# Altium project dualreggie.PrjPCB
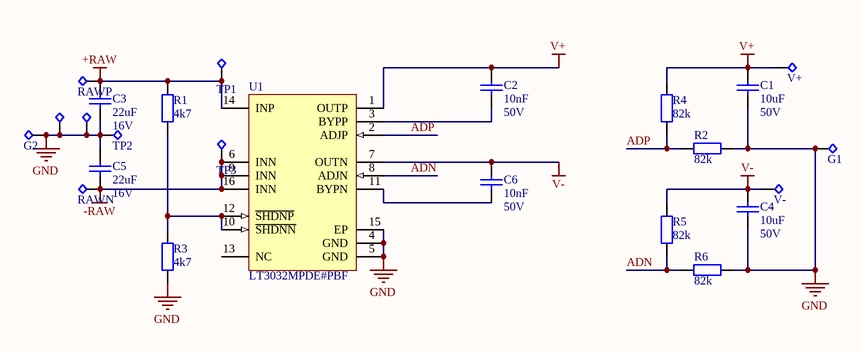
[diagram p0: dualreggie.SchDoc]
1 sheet, 24 parts. Net scope: global (net labels, ports and power ports of the same name join across sheets).
Board file: dualreggie.PcbDoc

## Sheet dualreggie.SchDoc
size A0

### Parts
C1  10uF  Voltage rating: 50V  [CC1210N1X]
C2  10nF  Voltage rating: 50V  [CC0402N1X]
C3  22uF  Voltage rating: 16V  [CC0805N1R]
C4  10uF  Voltage rating: 50V  [CC1210N1X]
C5  22uF  Voltage rating: 16V  [CC0805N1R]
C6  10nF  Voltage rating: 50V  [CC0402N1X]
G1  TP 0.5mm  [SP2.0]  (value not drawn)  (no BOM)
G2  TP 0.5mm  [SP2.0]  (value not drawn)  (no BOM)
GND1  TP 0.5mm  [TPH0.5S]  (value not drawn)  (no BOM)
GND2  TP 0.5mm  [TPH0.5S]  (value not drawn)  (no BOM)
R1  4k7  [RC0402N1R]
R2  82k  [RC0402N1R]
R3  4k7  [RC0402N1R]
R4  82k  [RC0402N1R]
R5  82k  [RC0402N1R]
R6  82k  [RC0402N1R]
RAWN  TP 0.5mm  [SP2.0]  (value not drawn)  (no BOM)
RAWP  TP 0.5mm  [SP2.0]  (value not drawn)  (no BOM)
TP1  TP 0.5mm  [TPH0.5S]  (value not drawn)  (no BOM)
TP2  TP 0.5mm  [TPH0.5S]  (value not drawn)  (no BOM)
TP3  TP 0.5mm  [TPH0.5S]  (value not drawn)  (no BOM)
U1  LT3032MPDE#PBF  [LT-DE14MA-14_V]
V+  TP 0.5mm  [SP2.0]  (value not drawn)  (no BOM)
V-  TP 0.5mm  [SP2.0]  (value not drawn)  (no BOM)

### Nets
+RAW: C3.2 R1.2 RAWP.1 TP1.1 U1.14(INP)
-RAW: C5.1 RAWN.1 TP3.1 U1.6(INN) U1.9(INN) U1.16(INN)
GND: C1.1 C3.1 C4.1 C5.2 G1.1 G2.1 GND1.1 GND2.1 R2.1 R3.1 R6.1 TP2.1 U1.4(GND) U1.5(GND) U1.15(EP)
V+: C1.2 C2.2 R4.2 U1.1(OUTP) V+.1
V-: C4.2 C6.2 R5.2 U1.7(OUTN) V-.1
ADN: R5.1 R6.2 U1.8(ADJN)
ADP: R2.2 R4.1 U1.2(ADJP)
NetC2_1: C2.1 U1.3(BYPP)
NetC6_1: C6.1 U1.11(BYPN)
NetR1_1: R1.1 R3.2 U1.10(~{SHDNN}) U1.12(~{SHDNP})

Not connected (* = marked no-connect by the designer): U1 13(NC)

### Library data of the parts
C1 C4 = CAPCC1210_10U_50VX7R: Capacitor chip ceramic 1210 50V X7R; Manufacturer: TDK; Manufacturer No: GRM32ER71H106KA12L; Tech: SMDR
C2 C6 = CAPCC0402_1_10.0N_50VX7R: Capacitor chip ceramic 0402 50V X7R; Manufacturer: Murata; Manufacturer No: GRM155R71H103KA88J; Tech: SMDR
C3 C5 = CAPCC0805_22U_16VX7R: Capacitor chip ceramic 0805 16V X7R; Manufacturer: Murata; Manufacturer No: GRM219R61C226ME15L; Tech: SMDR
G1 G2 GND1 GND2 RAWN RAWP TP1-TP3 V+ V- = ELE-TP0.5S: Test Point 0.5mm Slim; Sort: 610; Tech: THDW
R1 R3 = RES0402-1-4.7K-1%100PPM: Chip Resistor 0402 62.5mW 1% 100ppm; Manufacturer: Panasonic; Manufacturer No: ERJ-2RKF4701X; Tech: SMDR
R2 R4-R6 = RES0402-1-82K-1%100PPM: Chip Resistor 0402 62.5mW 1% 100ppm; Manufacturer: Panasonic; Manufacturer No: ERJ-2RKF8202X; Tech: SMDR
U1 = LT3032MPDE#PBF: Dual 150 mA Positive / Negative Low Noise Low Dropout Linear Regulator, +/-2.3 to +/-20 V Vin, Adjustable Vout, 14-pin SON (DE14MA-14), -55 to 125 degC, Pb-Free; Manufacturer: Linear Technology; Discrete Pass Element: no; Dropout Voltage(V): 0.3; Iout(mA): 150; Isupply(mA): 0.025; Noise(uV): 30; Number of Outputs: 2; Output Voltage: Adj,-Adj; PSRR(dB): 68; Shutdown Current(uA): 0.1; Vout Min(V): +/-1.22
